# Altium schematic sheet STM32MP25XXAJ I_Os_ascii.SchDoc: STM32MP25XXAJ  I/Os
size A3; Date: Not used; ApprovedBy: Not used; CheckedBy: Not used; Author: Not used; CompanyName: STMicroelectronics; DrawnBy: Not used; Engineer: Not used; Organization: Not used; Address1: Not used; Address2: Not used; Address3: Not used; Address4: Not used; DocumentNumber: 3; Revision: Not used; SheetNumber: 3; SheetTotal: 7
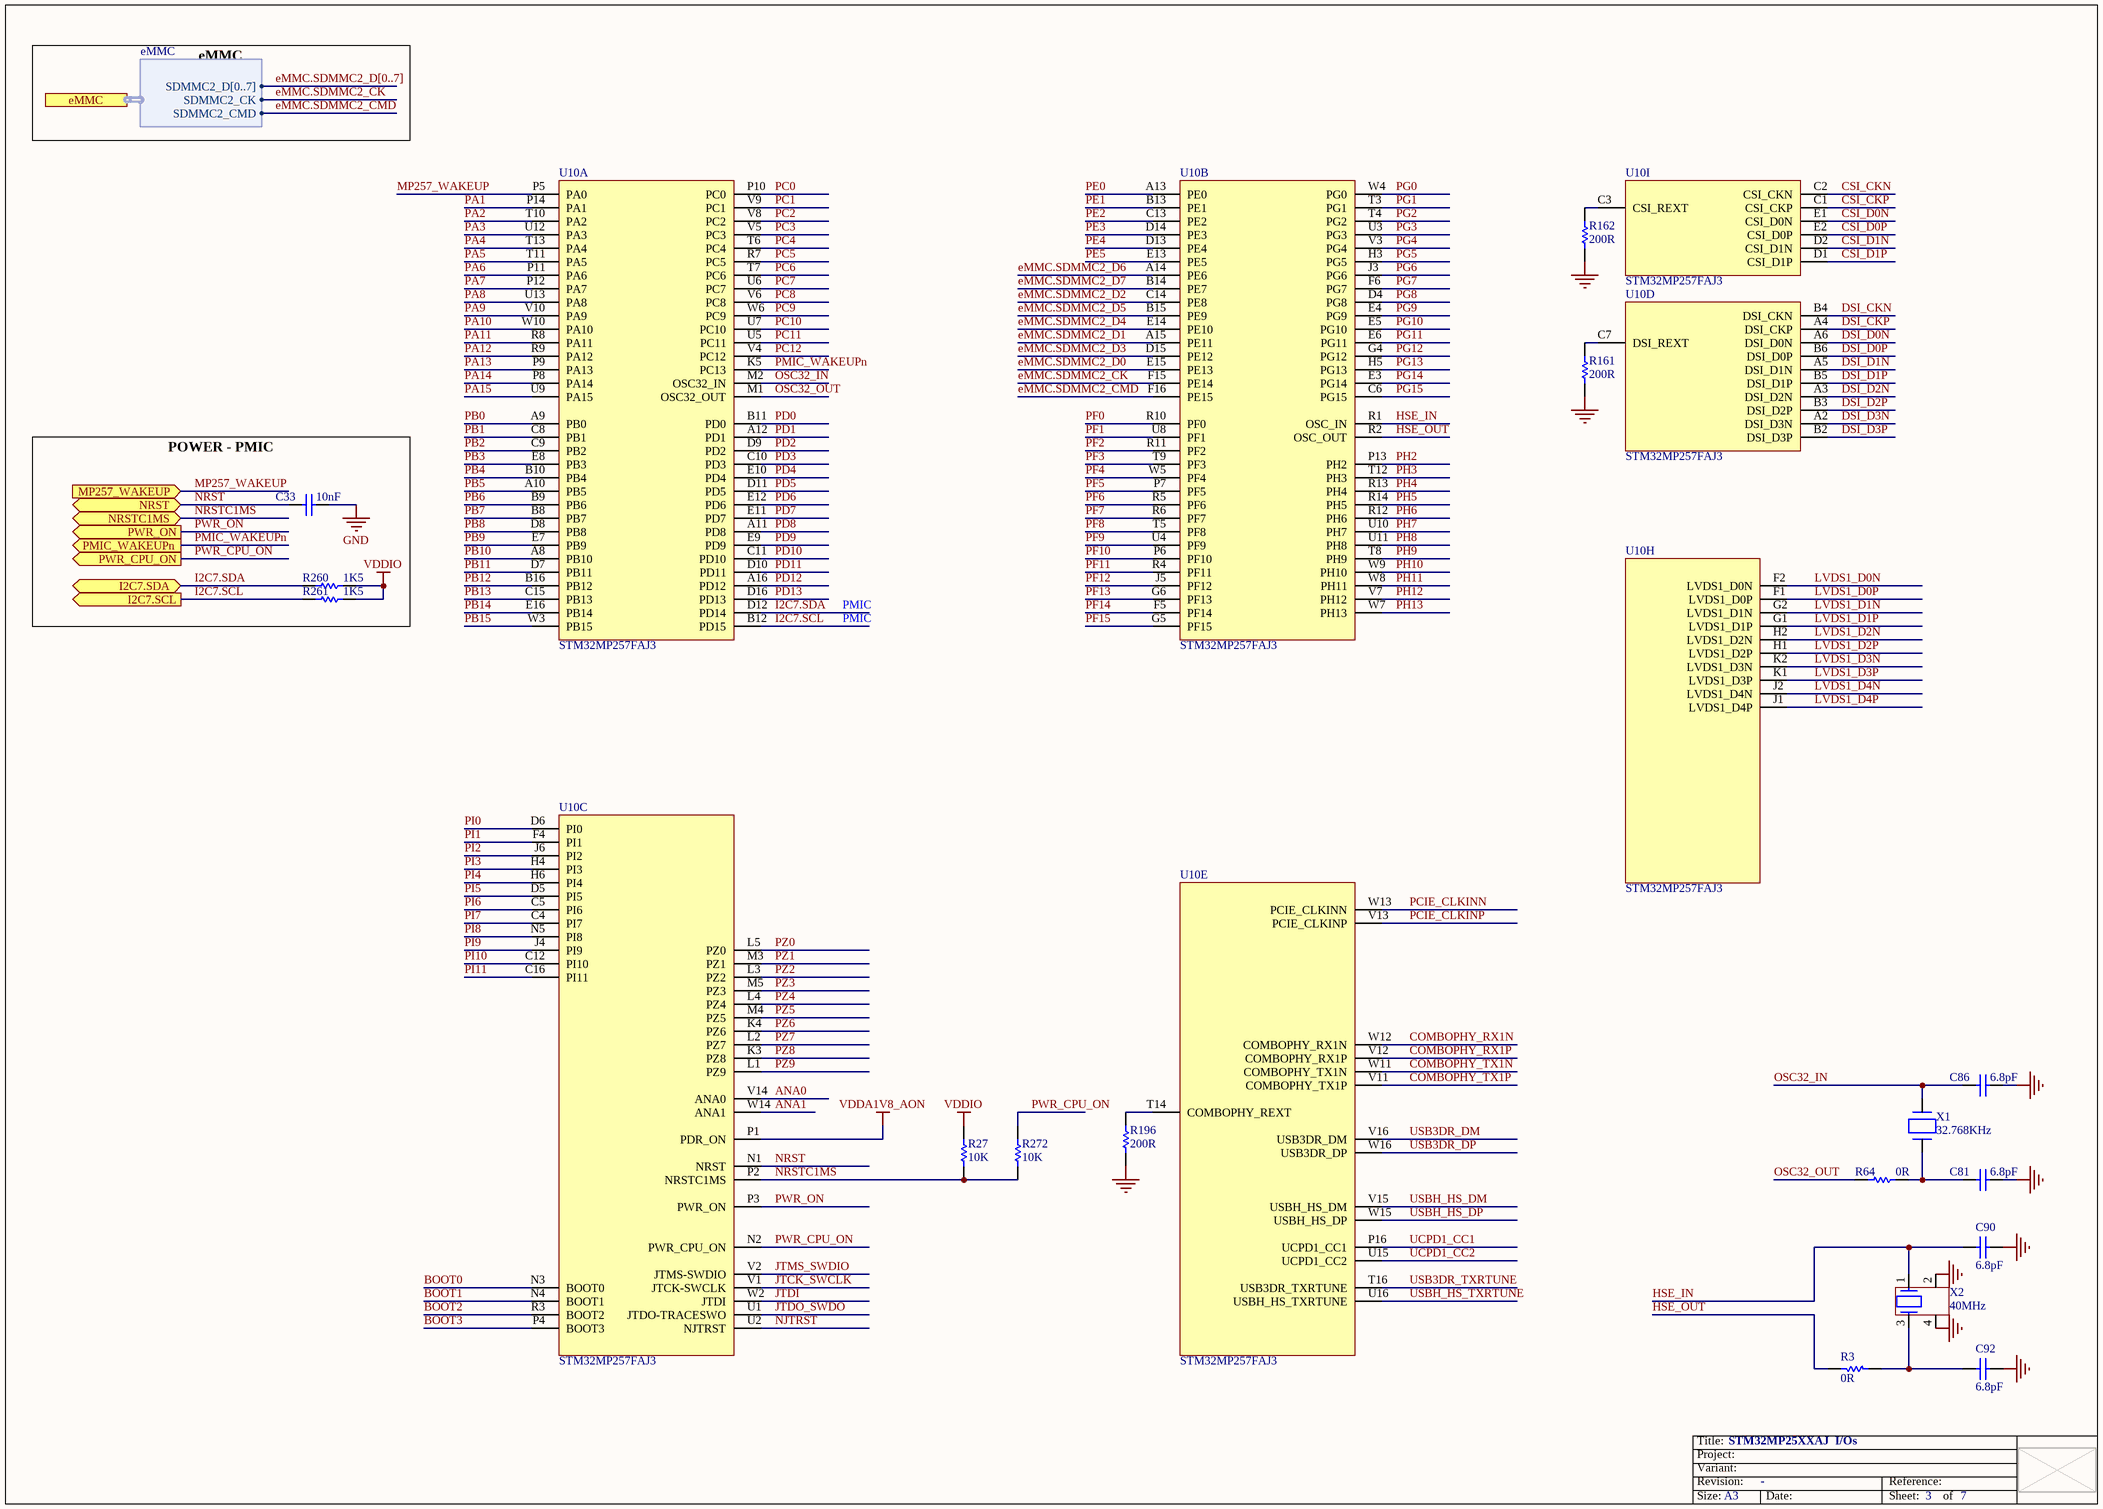
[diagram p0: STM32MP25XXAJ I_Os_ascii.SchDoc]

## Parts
C33  value 10nF  [C0402]  (hidden comment: Capacitor)
C81  value 6.8pF  [C0402]  (hidden comment: Capacitor)
C86  value 6.8pF  [C0402]  (hidden comment: Capacitor)
C90  value 6.8pF  [C0402]  (hidden comment: Capacitor)
C92  value 6.8pF  [C0402]  (hidden comment: Capacitor)
R3  value 0R  [R0402]
R27  value 10K  [R0402]  (hidden comment: Resistor)
R64  value 0R  [R0402]
R161  value 200R  [R0402]  (hidden comment: Resistor)
R162  value 200R  [R0402]  (hidden comment: Resistor)
R196  value 200R  [R0402]  (hidden comment: Resistor)
R260  value 1K5  [R0402]  (hidden comment: Resistor)
R261  value 1K5  [R0402]  (hidden comment: Resistor)
R272  value 10K  [R0402]  (hidden comment: Resistor)
U10  value STM32MP257FAJ3  [ICC_TFBGA361_16X16_P080]  (hidden comment: IC_STM32MP257FAJ3)  (parts A,B,C,D,E,H,I of 9)
X1  value 32.768KHz  [CRY_NX2012SA_2P]  (hidden comment: XTAL_2_PINS)
X2  value 40MHz  [CRY_NX1612SA_4P]  (hidden comment: XTAL_4_PINS)

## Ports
eMMC (harness eMMC), I2C7.SCL (out), I2C7.SDA (bidir), MP257_WAKEUP (in), NRST (bidir), NRSTC1MS (bidir), PMIC_WAKEUPn (out), PWR_CPU_ON (out), PWR_ON (out)

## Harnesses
eMMC: SDMMC2_CK, SDMMC2_CMD, SDMMC2_D[0..7]

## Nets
GND: C33.1 C81.2 C86.2 C90.1 C92.2 R161.2 R162.2 R196.1 X2.2 X2.4
VDDA1V8_AON: U10.P1(PDR_ON)
VDDIO: R27.2 R260.2 R261.2
ANA0: U10.V14(ANA0)
ANA1: U10.W14(ANA1)
BOOT0: U10.N3(BOOT0)
BOOT1: U10.N4(BOOT1)
BOOT2: U10.R3(BOOT2)
BOOT3: U10.P4(BOOT3)
COMBOPHY_RX1N: U10.W12(COMBOPHY_RX1N)
COMBOPHY_RX1P: U10.V12(COMBOPHY_RX1P)
COMBOPHY_TX1N: U10.W11(COMBOPHY_TX1N)
COMBOPHY_TX1P: U10.V11(COMBOPHY_TX1P)
CSI_CKN: U10.C2(CSI_CKN)
CSI_CKP: U10.C1(CSI_CKP)
CSI_D0N: U10.E1(CSI_D0N)
CSI_D0P: U10.E2(CSI_D0P)
CSI_D1N: U10.D2(CSI_D1N)
CSI_D1P: U10.D1(CSI_D1P)
DSI_CKN: U10.B4(DSI_CKN)
DSI_CKP: U10.A4(DSI_CKP)
DSI_D0N: U10.A6(DSI_D0N)
DSI_D0P: U10.B6(DSI_D0P)
DSI_D1N: U10.A5(DSI_D1N)
DSI_D1P: U10.B5(DSI_D1P)
DSI_D2N: U10.A3(DSI_D2N)
DSI_D2P: U10.B3(DSI_D2P)
DSI_D3N: U10.A2(DSI_D3N)
DSI_D3P: U10.B2(DSI_D3P)
eMMC.SDMMC2_CK: U10.F15(PE14) ; port eMMC.SDMMC2_CK
eMMC.SDMMC2_CMD: U10.F16(PE15) ; port eMMC.SDMMC2_CMD
eMMC.SDMMC2_D0: U10.E15(PE13)
eMMC.SDMMC2_D1: U10.A15(PE11)
eMMC.SDMMC2_D2: U10.C14(PE8)
eMMC.SDMMC2_D3: U10.D15(PE12)
eMMC.SDMMC2_D4: U10.E14(PE10)
eMMC.SDMMC2_D5: U10.B15(PE9)
eMMC.SDMMC2_D6: U10.A14(PE6)
eMMC.SDMMC2_D7: U10.B14(PE7)
HSE_IN: C90.2 U10.R1(OSC_IN) X2.1
HSE_OUT: R3.2 U10.R2(OSC_OUT)
I2C7.SCL: R261.1 U10.B12(PD15) ; port I2C7.SCL
I2C7.SDA: R260.1 U10.D12(PD14) ; port I2C7.SDA
JTCK_SWCLK: U10.V1(JTCK-SWCLK)
JTDI: U10.W2(JTDI)
JTDO_SWDO: U10.U1(JTDO-TRACESWO)
JTMS_SWDIO: U10.V2(JTMS-SWDIO)
LVDS1_D0N: U10.F2(LVDS1_D0N)
LVDS1_D0P: U10.F1(LVDS1_D0P)
LVDS1_D1N: U10.G2(LVDS1_D1N)
LVDS1_D1P: U10.G1(LVDS1_D1P)
LVDS1_D2N: U10.H2(LVDS1_D2N)
LVDS1_D2P: U10.H1(LVDS1_D2P)
LVDS1_D3N: U10.K2(LVDS1_D3N)
LVDS1_D3P: U10.K1(LVDS1_D3P)
LVDS1_D4N: U10.J2(LVDS1_D4N)
LVDS1_D4P: U10.J1(LVDS1_D4P)
MP257_WAKEUP: U10.P5(PA0) ; port MP257_WAKEUP
NJTRST: U10.U2(NJTRST)
NRST: C33.2 U10.N1(NRST) ; port NRST
NRSTC1MS: R27.1 R272.1 U10.P2(NRSTC1MS) ; port NRSTC1MS
OSC32_IN: C86.1 U10.M2(OSC32_IN) X1.2(X2)
OSC32_OUT: R64.1 U10.M1(OSC32_OUT)
PA1: U10.P14(PA1)
PA2: U10.T10(PA2)
PA3: U10.U12(PA3)
PA4: U10.T13(PA4)
PA5: U10.T11(PA5)
PA6: U10.P11(PA6)
PA7: U10.P12(PA7)
PA8: U10.U13(PA8)
PA9: U10.V10(PA9)
PA10: U10.W10(PA10)
PA11: U10.R8(PA11)
PA12: U10.R9(PA12)
PA13: U10.P9(PA13)
PA14: U10.P8(PA14)
PA15: U10.U9(PA15)
PB0: U10.A9(PB0)
PB1: U10.C8(PB1)
PB2: U10.C9(PB2)
PB3: U10.E8(PB3)
PB4: U10.B10(PB4)
PB5: U10.A10(PB5)
PB6: U10.B9(PB6)
PB7: U10.B8(PB7)
PB8: U10.D8(PB8)
PB9: U10.E7(PB9)
PB10: U10.A8(PB10)
PB11: U10.D7(PB11)
PB12: U10.B16(PB12)
PB13: U10.C15(PB13)
PB14: U10.E16(PB14)
PB15: U10.W3(PB15)
PC0: U10.P10(PC0)
PC1: U10.V9(PC1)
PC2: U10.V8(PC2)
PC3: U10.V5(PC3)
PC4: U10.T6(PC4)
PC5: U10.R7(PC5)
PC6: U10.T7(PC6)
PC7: U10.U6(PC7)
PC8: U10.V6(PC8)
PC9: U10.W6(PC9)
PC10: U10.U7(PC10)
PC11: U10.U5(PC11)
PC12: U10.V4(PC12)
PCIE_CLKINN: U10.W13(PCIE_CLKINN)
PCIE_CLKINP: U10.V13(PCIE_CLKINP)
PD0: U10.B11(PD0)
PD1: U10.A12(PD1)
PD2: U10.D9(PD2)
PD3: U10.C10(PD3)
PD4: U10.E10(PD4)
PD5: U10.D11(PD5)
PD6: U10.E12(PD6)
PD7: U10.E11(PD7)
PD8: U10.A11(PD8)
PD9: U10.E9(PD9)
PD10: U10.C11(PD10)
PD11: U10.D10(PD11)
PD12: U10.A16(PD12)
PD13: U10.D16(PD13)
PE0: U10.A13(PE0)
PE1: U10.B13(PE1)
PE2: U10.C13(PE2)
PE3: U10.D14(PE3)
PE4: U10.D13(PE4)
PE5: U10.E13(PE5)
PF0: U10.R10(PF0)
PF1: U10.U8(PF1)
PF2: U10.R11(PF2)
PF3: U10.T9(PF3)
PF4: U10.W5(PF4)
PF5: U10.P7(PF5)
PF6: U10.R5(PF6)
PF7: U10.R6(PF7)
PF8: U10.T5(PF8)
PF9: U10.U4(PF9)
PF10: U10.P6(PF10)
PF11: U10.R4(PF11)
PF12: U10.J5(PF12)
PF13: U10.G6(PF13)
PF14: U10.F5(PF14)
PF15: U10.G5(PF15)
PG0: U10.W4(PG0)
PG1: U10.T3(PG1)
PG2: U10.T4(PG2)
PG3: U10.U3(PG3)
PG4: U10.V3(PG4)
PG5: U10.H3(PG5)
PG6: U10.J3(PG6)
PG7: U10.F6(PG7)
PG8: U10.D4(PG8)
PG9: U10.E4(PG9)
PG10: U10.E5(PG10)
PG11: U10.E6(PG11)
PG12: U10.G4(PG12)
PG13: U10.H5(PG13)
PG14: U10.E3(PG14)
PG15: U10.C6(PG15)
PH2: U10.P13(PH2)
PH3: U10.T12(PH3)
PH4: U10.R13(PH4)
PH5: U10.R14(PH5)
PH6: U10.R12(PH6)
PH7: U10.U10(PH7)
PH8: U10.U11(PH8)
PH9: U10.T8(PH9)
PH10: U10.W9(PH10)
PH11: U10.W8(PH11)
PH12: U10.V7(PH12)
PH13: U10.W7(PH13)
PI0: U10.D6(PI0)
PI1: U10.F4(PI1)
PI2: U10.J6(PI2)
PI3: U10.H4(PI3)
PI4: U10.H6(PI4)
PI5: U10.D5(PI5)
PI6: U10.C5(PI6)
PI7: U10.C4(PI7)
PI8: U10.N5(PI8)
PI9: U10.J4(PI9)
PI10: U10.C12(PI10)
PI11: U10.C16(PI11)
PMIC_WAKEUPn: U10.K5(PC13) ; port PMIC_WAKEUPn
PWR_CPU_ON: R272.2 U10.N2(PWR_CPU_ON) ; port PWR_CPU_ON
PWR_ON: U10.P3(PWR_ON) ; port PWR_ON
PZ0: U10.L5(PZ0)
PZ1: U10.M3(PZ1)
PZ2: U10.L3(PZ2)
PZ3: U10.M5(PZ3)
PZ4: U10.L4(PZ4)
PZ5: U10.M4(PZ5)
PZ6: U10.K4(PZ6)
PZ7: U10.L2(PZ7)
PZ8: U10.K3(PZ8)
PZ9: U10.L1(PZ9)
UCPD1_CC1: U10.P16(UCPD1_CC1)
UCPD1_CC2: U10.U15(UCPD1_CC2)
USB3DR_DM: U10.V16(USB3DR_DM)
USB3DR_DP: U10.W16(USB3DR_DP)
USB3DR_TXRTUNE: U10.T16(USB3DR_TXRTUNE)
USBH_HS_DM: U10.V15(USBH_HS_DM)
USBH_HS_DP: U10.W15(USBH_HS_DP)
USBH_HS_TXRTUNE: U10.U16(USBH_HS_TXRTUNE)
NetC81_1: C81.1 R64.2 X1.1(X1)
NetC92_1: C92.1 R3.1 X2.3
NetR161_1: R161.1 U10.C7(DSI_REXT)
NetR162_1: R162.1 U10.C3(CSI_REXT)
NetR196_2: R196.2 U10.T14(COMBOPHY_REXT)

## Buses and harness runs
bus eMMC.SDMMC2_D[0..7]

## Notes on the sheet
- eMMC
- POWER - PMIC
- PMIC

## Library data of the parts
C33 = MCD-00011: Capacitor, MLCC, 10nF, 16V, X7R, 10%, 0402, T=0.5mm; Manufacturer_Part_Number: CC0402KRX7R7BB103; Manufacturer: YAGEO; Provided_By: SUBCO; Initial_Board_Reference: MB1274
C81 C86 = MCD-00674: Capacitor, MLCC, 6.8pF, 50V, NPO, +-0.25pF, 0402, T=0.5mm; Manufacturer_Part_Number: CC0402CRNPO9BN6R8; Manufacturer: YAGEO; Part_Preference: Recommended; Provided_By: SUBCO; Initial_Board_Reference: MB1319; Path: ws/MCD_ApplicationBoards/Lists/MCDPARTSdatabase; Item Type: Item; Component_Country_Of_Origin: China; ID: 3068; ShowFields: YES
C90 C92 = MCD-00674: Capacitor, MLCC, 6.8pF, 50V, NPO, +-0.25pF, 0402, T=0.5mm; Manufacturer_Part_Number: CC0402CRNPO9BN6R8; Manufacturer: YAGEO; Part_Preference: Recommended; Provided_By: SUBCO; Initial_Board_Reference: MB1319; Component_Country_Of_Origin: China; ID: 3068; ShowFields: YES
R3 R64 = MCD-00052: Resistor,0R,0402,5%,1/16W; Manufacturer_Part_Number: RC0402JR-070RL; Manufacturer: YAGEO; Part_Preference: Recommended; Provided_By: SUBCO; Initial_Board_Reference: mb1274; Order_Code_RS: 618-5804; Component_Country_Of_Origin: China; ID: 2540; ShowFields: YES
R27 R272 = MCD-00053: Resistor,10K,0402,1%,1/16W; BMS_Part_Number: 9131590; Part_Preference: Recommended; Manufacturer: YAGEO; Manufacturer_Part_Number: RC0402FR-0710KL; Component_Country_Of_Origin: China; ID: 2539; ShowFields: YES
R161 R162 = MCD-00417: Resistor,200R,0402,1%,1/16W; Manufacturer_Part_Number: RC0402FR-07200RL; Manufacturer: YAGEO; Part_Preference: Recommended; ECCN_US: EAR99; ECCN_EU: NEC; Provided_By: SUBCO
R196 = MCD-00417: Resistor,200R,0402,1%,1/16W; Part_Preference: Recommended; Manufacturer: YAGEO; Manufacturer_Part_Number: RC0402FR-07200RL
R260 R261 = MCD-00068: Resistor,1K5,0402,1%,1/16W; Part_Preference: Recommended; Manufacturer: YAGEO; Manufacturer_Part_Number: RC0402FR-071K5L; Component_Country_Of_Origin: China; ID: 2524; ShowFields: YES
U10 = MCD-04441: MPU, Dual Core ARM cortex-A35 64-bit + M33 32-bit,  808KB SRAM, With Crypto; Part_Type: IC; Part_Preference: Recommended; Manufacturer: STMICROELECTRONICS; ShowFields: YES; ID: 6557
X1 = MCD-01479: Crystal, 32.768kHz, 6pF, +/-20ppm, 80K, 2.05x1.2mm; BMS_Part_Number: 9157049; Part_Type: Crystal_Osc; Part_Preference: Recommended; Manufacturer: NDK; Manufacturer_Part_Number: NX2012SA-32.768KHZ-EXS00A-MU00527; Component_Country_Of_Origin: Unknown; ShowFields: YES; ID: 3579
X2 = MCD-02344: Crystal, 40MHz, 6pF, +/-20ppm, 80R, 1.6x1.2mm; Part_Type: Crystal_Osc; Part_Preference: Recommended; Manufacturer: NDK; Manufacturer_Part_Number: NX1612SA-40MHZ-EXS00A-CS13836; Component_Country_Of_Origin: Unknown; ShowFields: YES; ID: 4450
